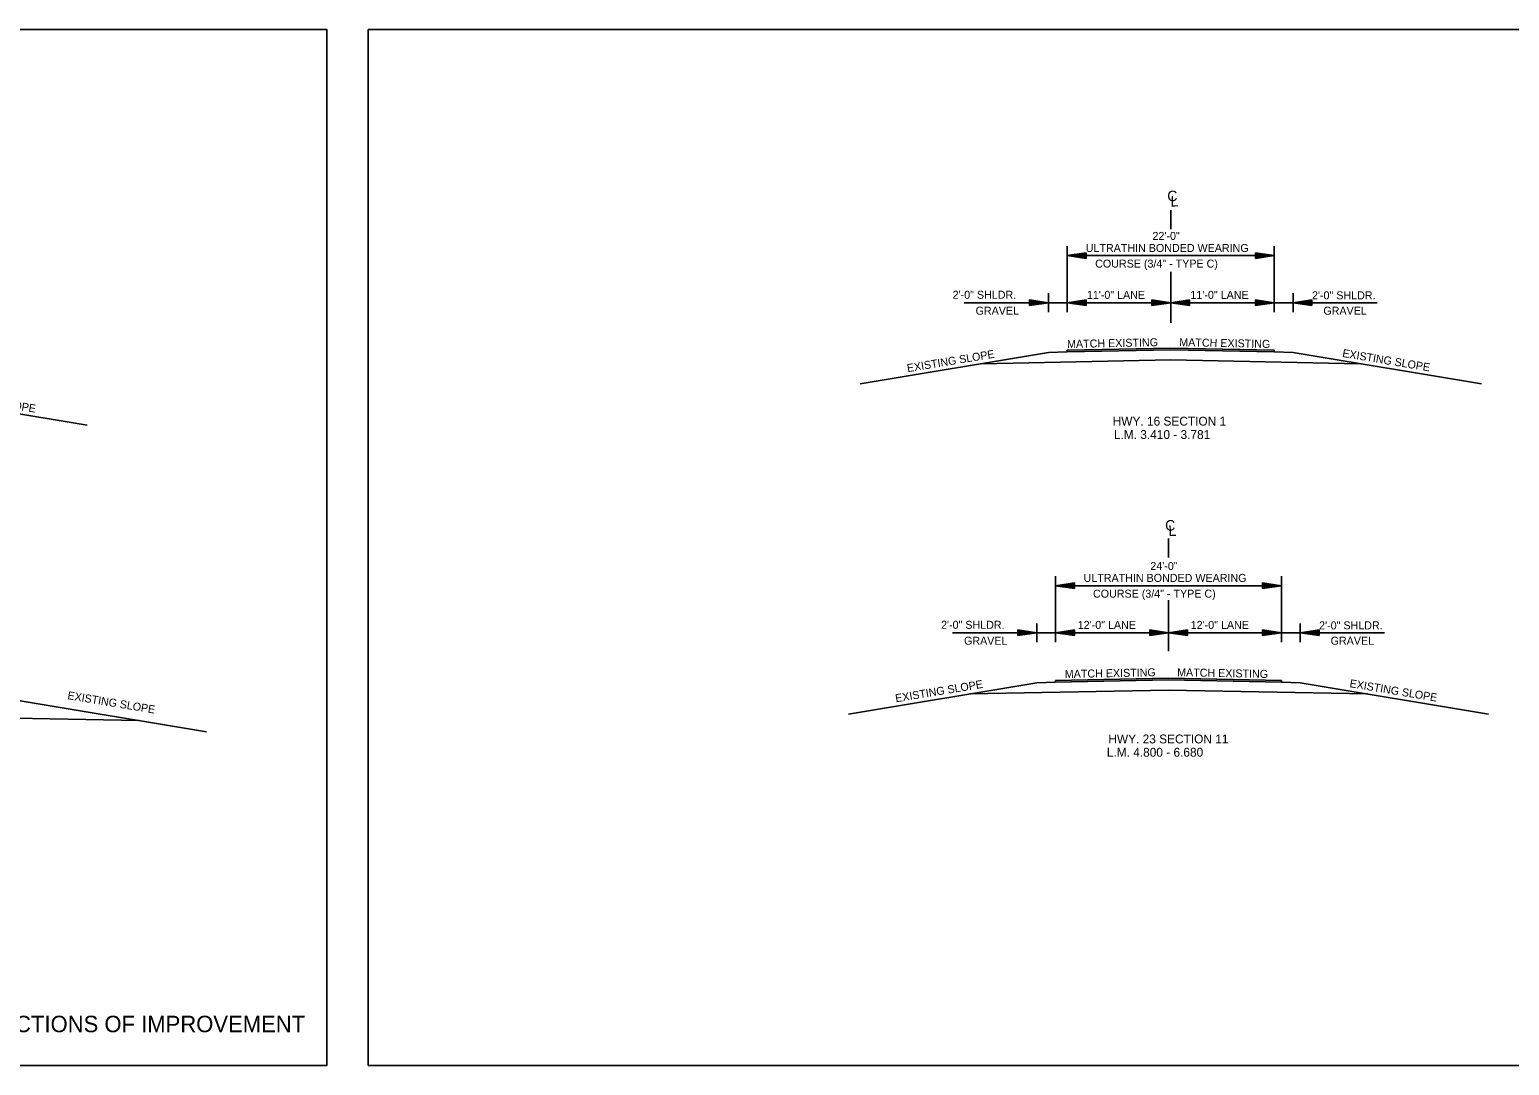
# Model space of a CAD drawing. Extents: x 2261938 to 2263136, y -3124572 to -3124216.
# Drawn here: x 2262466.5 to 2262623.7, y -3124556.1 to -3124446.1 of the extents above; entities that cross this region are included whole.
import ezdxf

# ---------------------------------------------------------------- set-up
doc = ezdxf.new("R2010")
doc.units = 0
for name, color, linetype in [('DSN_DRFT_Common-Annotations', 7, 'Continuous'), ('DSN_DRFT_Common-Line', 7, 'Continuous'), ('DSN_DRFT_Dimension', 7, 'Continuous'), ('SHET_Border-Text', 7, 'Continuous')]:
    doc.layers.add(name, color=color, linetype=linetype)

msp = doc.modelspace()

# ---------------------------------------------------------------- linework, layer by layer
at = {"layer": 'DSN_DRFT_Common-Line'}
for p, q in [((2262587.74, -3124465.28), (2262587.74, -3124467.3)), ((2262576.74, -3124469.11), (2262576.74, -3124476.11)), ((2262598.74, -3124469.11), (2262598.74, -3124476.11)), ((2262587.74, -3124471.82), (2262587.74, -3124477.23)), ((2262574.74, -3124474.11), (2262574.74, -3124476.11)), ((2262600.74, -3124474.11), (2262600.74, -3124476.11)), ((2262574.74, -3124480.41), (2262554.74, -3124483.74)), ((2262587.74, -3124481.19), (2262567.63, -3124481.6)), ((2262576.74, -3124480.33), (2262574.74, -3124480.41)), ((2262587.74, -3124479.94), (2262576.74, -3124480.16)), ((2262587.74, -3124480.11), (2262576.74, -3124480.33)), ((2262576.74, -3124480.16), (2262576.74, -3124480.33)), ((2262587.74, -3124479.94), (2262598.74, -3124480.16)), ((2262587.74, -3124480.11), (2262598.74, -3124480.33)), ((2262587.74, -3124481.19), (2262607.85, -3124481.6)), ((2262598.74, -3124480.16), (2262598.74, -3124480.33)), ((2262598.74, -3124480.33), (2262600.74, -3124480.41)), ((2262600.74, -3124480.41), (2262620.74, -3124483.74)), ((2262452.66, -3124484.8), (2262472.66, -3124488.13)), ((2262587.5, -3124500.15), (2262587.5, -3124502.18)), ((2262575.5, -3124504.16), (2262575.5, -3124511.16)), ((2262599.5, -3124504.16), (2262599.5, -3124511.16)), ((2262587.5, -3124506.7), (2262587.5, -3124512.11)), ((2262573.5, -3124509.16), (2262573.5, -3124511.16)), ((2262601.5, -3124509.16), (2262601.5, -3124511.16)), ((2262573.5, -3124515.48), (2262553.5, -3124518.81)), ((2262575.5, -3124515.4), (2262573.5, -3124515.48)), ((2262587.5, -3124515.16), (2262575.5, -3124515.4)), ((2262587.5, -3124515.16), (2262599.5, -3124515.4)), ((2262599.5, -3124515.4), (2262601.5, -3124515.48)), ((2262601.5, -3124515.48), (2262621.5, -3124518.81)), ((2262465.33, -3124517.35), (2262485.33, -3124520.68)), ((2262587.5, -3124516.24), (2262566.39, -3124516.66)), ((2262587.5, -3124516.24), (2262608.62, -3124516.66)), ((2262391.33, -3124517.75), (2262478.16, -3124519.49))]:
    msp.add_line(p, q, dxfattribs=at)
for points in [[(2262328.11, -3124446.1), (2262328.11, -3124556.1), (2262498.11, -3124556.1), (2262498.11, -3124446.1)], [(2262502.5, -3124446.1), (2262502.5, -3124556.1), (2262672.5, -3124556.1), (2262672.5, -3124446.1)], [(2262598.74, -3124480.33), (2262587.74, -3124480.11), (2262576.74, -3124480.33), (2262576.74, -3124480.16), (2262587.74, -3124479.94), (2262598.74, -3124480.16)], [(2262599.5, -3124515.4), (2262587.5, -3124515.16), (2262575.5, -3124515.4), (2262575.5, -3124515.23), (2262587.5, -3124514.99), (2262599.5, -3124515.23)]]:
    msp.add_lwpolyline(points, close=True, dxfattribs=at)
at = {"layer": 'DSN_DRFT_Dimension'}
for p, q in [((2262578.74, -3124469.81), (2262576.74, -3124470.11)), ((2262578.74, -3124470.41), (2262576.74, -3124470.11)), ((2262576.74, -3124470.11), (2262598.74, -3124470.11)), ((2262578.74, -3124469.86), (2262577.07, -3124470.11)), ((2262578.74, -3124470.36), (2262577.07, -3124470.11)), ((2262578.74, -3124469.91), (2262577.42, -3124470.11)), ((2262578.74, -3124470.31), (2262577.42, -3124470.11)), ((2262578.74, -3124469.96), (2262577.75, -3124470.11)), ((2262578.74, -3124470.26), (2262577.75, -3124470.11)), ((2262578.74, -3124470.01), (2262578.09, -3124470.11)), ((2262578.74, -3124470.21), (2262578.09, -3124470.11)), ((2262578.74, -3124470.06), (2262578.42, -3124470.11)), ((2262578.74, -3124470.16), (2262578.42, -3124470.11)), ((2262578.74, -3124469.81), (2262578.74, -3124470.41)), ((2262596.74, -3124469.81), (2262598.74, -3124470.11)), ((2262596.74, -3124469.81), (2262596.74, -3124470.41)), ((2262596.74, -3124469.86), (2262598.41, -3124470.11)), ((2262596.74, -3124469.91), (2262598.06, -3124470.11)), ((2262596.74, -3124469.96), (2262597.73, -3124470.11)), ((2262596.74, -3124470.01), (2262597.39, -3124470.11)), ((2262596.74, -3124470.06), (2262597.06, -3124470.11)), ((2262596.74, -3124470.41), (2262598.74, -3124470.11)), ((2262596.74, -3124470.21), (2262597.39, -3124470.11)), ((2262596.74, -3124470.31), (2262598.06, -3124470.11)), ((2262596.74, -3124470.36), (2262598.41, -3124470.11)), ((2262596.74, -3124470.26), (2262597.73, -3124470.11)), ((2262596.74, -3124470.16), (2262597.06, -3124470.11)), ((2262572.74, -3124474.81), (2262574.74, -3124475.11)), ((2262572.74, -3124474.81), (2262572.74, -3124475.41)), ((2262572.74, -3124474.86), (2262574.41, -3124475.11)), ((2262572.74, -3124474.91), (2262574.06, -3124475.11)), ((2262572.74, -3124474.96), (2262573.73, -3124475.11)), ((2262572.74, -3124475.01), (2262573.39, -3124475.11)), ((2262578.74, -3124474.81), (2262576.74, -3124475.11)), ((2262578.74, -3124474.86), (2262577.07, -3124475.11)), ((2262578.74, -3124474.91), (2262577.42, -3124475.11)), ((2262578.74, -3124474.96), (2262577.75, -3124475.11)), ((2262578.74, -3124475.01), (2262578.09, -3124475.11)), ((2262578.74, -3124474.81), (2262578.74, -3124475.41)), ((2262585.74, -3124474.81), (2262587.74, -3124475.11)), ((2262585.74, -3124474.81), (2262585.74, -3124475.41)), ((2262585.74, -3124474.86), (2262587.41, -3124475.11)), ((2262585.74, -3124474.91), (2262587.06, -3124475.11)), ((2262585.74, -3124474.96), (2262586.73, -3124475.11)), ((2262585.74, -3124475.01), (2262586.39, -3124475.11)), ((2262589.74, -3124474.81), (2262587.74, -3124475.11)), ((2262589.74, -3124474.86), (2262588.07, -3124475.11)), ((2262589.74, -3124474.91), (2262588.42, -3124475.11)), ((2262589.74, -3124474.96), (2262588.75, -3124475.11)), ((2262589.74, -3124475.01), (2262589.09, -3124475.11)), ((2262589.74, -3124474.81), (2262589.74, -3124475.41)), ((2262596.74, -3124474.81), (2262598.74, -3124475.11)), ((2262596.74, -3124474.81), (2262596.74, -3124475.41)), ((2262596.74, -3124474.86), (2262598.41, -3124475.11)), ((2262596.74, -3124474.91), (2262598.06, -3124475.11)), ((2262596.74, -3124474.96), (2262597.73, -3124475.11)), ((2262596.74, -3124475.01), (2262597.39, -3124475.11)), ((2262602.74, -3124474.81), (2262600.74, -3124475.11)), ((2262602.74, -3124474.86), (2262601.07, -3124475.11)), ((2262602.74, -3124474.91), (2262601.42, -3124475.11)), ((2262602.74, -3124474.96), (2262601.75, -3124475.11)), ((2262602.74, -3124475.01), (2262602.09, -3124475.11)), ((2262602.74, -3124474.81), (2262602.74, -3124475.41)), ((2262565.8, -3124475.11), (2262574.74, -3124475.11)), ((2262572.74, -3124475.06), (2262573.06, -3124475.11)), ((2262572.74, -3124475.41), (2262574.74, -3124475.11)), ((2262572.74, -3124475.21), (2262573.39, -3124475.11)), ((2262572.74, -3124475.31), (2262574.06, -3124475.11)), ((2262572.74, -3124475.36), (2262574.41, -3124475.11)), ((2262572.74, -3124475.26), (2262573.73, -3124475.11)), ((2262572.74, -3124475.16), (2262573.06, -3124475.11)), ((2262576.74, -3124475.11), (2262574.74, -3124475.11)), ((2262576.74, -3124475.11), (2262587.74, -3124475.11)), ((2262578.74, -3124475.41), (2262576.74, -3124475.11)), ((2262578.74, -3124475.36), (2262577.07, -3124475.11)), ((2262578.74, -3124475.31), (2262577.42, -3124475.11)), ((2262578.74, -3124475.26), (2262577.75, -3124475.11)), ((2262578.74, -3124475.21), (2262578.09, -3124475.11)), ((2262578.74, -3124475.06), (2262578.42, -3124475.11)), ((2262578.74, -3124475.16), (2262578.42, -3124475.11)), ((2262585.74, -3124475.06), (2262586.06, -3124475.11)), ((2262585.74, -3124475.41), (2262587.74, -3124475.11)), ((2262585.74, -3124475.21), (2262586.39, -3124475.11)), ((2262585.74, -3124475.31), (2262587.06, -3124475.11)), ((2262585.74, -3124475.36), (2262587.41, -3124475.11)), ((2262585.74, -3124475.26), (2262586.73, -3124475.11)), ((2262585.74, -3124475.16), (2262586.06, -3124475.11)), ((2262587.74, -3124475.11), (2262598.74, -3124475.11)), ((2262589.74, -3124475.41), (2262587.74, -3124475.11)), ((2262589.74, -3124475.36), (2262588.07, -3124475.11)), ((2262589.74, -3124475.31), (2262588.42, -3124475.11)), ((2262589.74, -3124475.26), (2262588.75, -3124475.11)), ((2262589.74, -3124475.21), (2262589.09, -3124475.11)), ((2262589.74, -3124475.06), (2262589.42, -3124475.11)), ((2262589.74, -3124475.16), (2262589.42, -3124475.11)), ((2262596.74, -3124475.06), (2262597.06, -3124475.11)), ((2262596.74, -3124475.41), (2262598.74, -3124475.11)), ((2262596.74, -3124475.21), (2262597.39, -3124475.11)), ((2262596.74, -3124475.31), (2262598.06, -3124475.11)), ((2262596.74, -3124475.36), (2262598.41, -3124475.11)), ((2262596.74, -3124475.26), (2262597.73, -3124475.11)), ((2262596.74, -3124475.16), (2262597.06, -3124475.11)), ((2262598.74, -3124475.11), (2262600.74, -3124475.11)), ((2262602.74, -3124475.41), (2262600.74, -3124475.11)), ((2262600.74, -3124475.11), (2262609.68, -3124475.11)), ((2262602.74, -3124475.36), (2262601.07, -3124475.11)), ((2262602.74, -3124475.31), (2262601.42, -3124475.11)), ((2262602.74, -3124475.26), (2262601.75, -3124475.11)), ((2262602.74, -3124475.21), (2262602.09, -3124475.11)), ((2262602.74, -3124475.06), (2262602.42, -3124475.11)), ((2262602.74, -3124475.16), (2262602.42, -3124475.11)), ((2262577.5, -3124504.86), (2262575.5, -3124505.16)), ((2262577.5, -3124504.91), (2262575.84, -3124505.16)), ((2262577.5, -3124504.86), (2262577.5, -3124505.46)), ((2262597.5, -3124504.86), (2262599.5, -3124505.16)), ((2262597.5, -3124504.86), (2262597.5, -3124505.46)), ((2262597.5, -3124504.91), (2262599.17, -3124505.16)), ((2262577.5, -3124505.46), (2262575.5, -3124505.16)), ((2262575.5, -3124505.16), (2262599.5, -3124505.16)), ((2262577.5, -3124505.41), (2262575.84, -3124505.16)), ((2262577.5, -3124504.96), (2262576.18, -3124505.16)), ((2262577.5, -3124505.36), (2262576.18, -3124505.16)), ((2262577.5, -3124505.01), (2262576.52, -3124505.16)), ((2262577.5, -3124505.31), (2262576.52, -3124505.16)), ((2262577.5, -3124505.06), (2262576.85, -3124505.16)), ((2262577.5, -3124505.26), (2262576.85, -3124505.16)), ((2262577.5, -3124505.11), (2262577.19, -3124505.16)), ((2262577.5, -3124505.2), (2262577.19, -3124505.16)), ((2262597.5, -3124504.96), (2262598.83, -3124505.16)), ((2262597.5, -3124505.01), (2262598.49, -3124505.16)), ((2262597.5, -3124505.06), (2262598.15, -3124505.16)), ((2262597.5, -3124505.11), (2262597.82, -3124505.16)), ((2262597.5, -3124505.46), (2262599.5, -3124505.16)), ((2262597.5, -3124505.26), (2262598.15, -3124505.16)), ((2262597.5, -3124505.36), (2262598.83, -3124505.16)), ((2262597.5, -3124505.41), (2262599.17, -3124505.16)), ((2262597.5, -3124505.31), (2262598.49, -3124505.16)), ((2262597.5, -3124505.2), (2262597.82, -3124505.16)), ((2262564.56, -3124510.16), (2262573.5, -3124510.16)), ((2262571.5, -3124509.86), (2262573.5, -3124510.16)), ((2262571.5, -3124509.86), (2262571.5, -3124510.46)), ((2262571.5, -3124509.91), (2262573.17, -3124510.16)), ((2262571.5, -3124509.96), (2262572.83, -3124510.16)), ((2262571.5, -3124510.01), (2262572.49, -3124510.16)), ((2262571.5, -3124510.06), (2262572.15, -3124510.16)), ((2262571.5, -3124510.11), (2262571.82, -3124510.16)), ((2262571.5, -3124510.46), (2262573.5, -3124510.16)), ((2262571.5, -3124510.26), (2262572.15, -3124510.16)), ((2262571.5, -3124510.36), (2262572.83, -3124510.16)), ((2262571.5, -3124510.41), (2262573.17, -3124510.16)), ((2262571.5, -3124510.31), (2262572.49, -3124510.16)), ((2262571.5, -3124510.2), (2262571.82, -3124510.16)), ((2262575.5, -3124510.16), (2262573.5, -3124510.16)), ((2262577.5, -3124509.86), (2262575.5, -3124510.16)), ((2262575.5, -3124510.16), (2262587.5, -3124510.16)), ((2262577.5, -3124510.46), (2262575.5, -3124510.16)), ((2262577.5, -3124509.91), (2262575.84, -3124510.16)), ((2262577.5, -3124510.41), (2262575.84, -3124510.16)), ((2262577.5, -3124509.96), (2262576.18, -3124510.16)), ((2262577.5, -3124510.36), (2262576.18, -3124510.16)), ((2262577.5, -3124510.01), (2262576.52, -3124510.16)), ((2262577.5, -3124510.31), (2262576.52, -3124510.16)), ((2262577.5, -3124510.06), (2262576.85, -3124510.16)), ((2262577.5, -3124510.26), (2262576.85, -3124510.16)), ((2262577.5, -3124510.11), (2262577.19, -3124510.16)), ((2262577.5, -3124510.2), (2262577.19, -3124510.16)), ((2262577.5, -3124509.86), (2262577.5, -3124510.46)), ((2262585.5, -3124509.86), (2262587.5, -3124510.16)), ((2262585.5, -3124509.86), (2262585.5, -3124510.46)), ((2262585.5, -3124509.91), (2262587.17, -3124510.16)), ((2262585.5, -3124509.96), (2262586.83, -3124510.16)), ((2262585.5, -3124510.01), (2262586.49, -3124510.16)), ((2262585.5, -3124510.06), (2262586.15, -3124510.16)), ((2262585.5, -3124510.11), (2262585.82, -3124510.16)), ((2262585.5, -3124510.46), (2262587.5, -3124510.16)), ((2262585.5, -3124510.26), (2262586.15, -3124510.16)), ((2262585.5, -3124510.36), (2262586.83, -3124510.16)), ((2262585.5, -3124510.41), (2262587.17, -3124510.16)), ((2262585.5, -3124510.31), (2262586.49, -3124510.16)), ((2262585.5, -3124510.2), (2262585.82, -3124510.16)), ((2262589.5, -3124509.86), (2262587.5, -3124510.16)), ((2262587.5, -3124510.16), (2262599.5, -3124510.16)), ((2262589.5, -3124510.46), (2262587.5, -3124510.16)), ((2262589.5, -3124509.91), (2262587.84, -3124510.16)), ((2262589.5, -3124510.41), (2262587.84, -3124510.16)), ((2262589.5, -3124509.96), (2262588.18, -3124510.16)), ((2262589.5, -3124510.36), (2262588.18, -3124510.16)), ((2262589.5, -3124510.01), (2262588.52, -3124510.16)), ((2262589.5, -3124510.31), (2262588.52, -3124510.16)), ((2262589.5, -3124510.06), (2262588.85, -3124510.16)), ((2262589.5, -3124510.26), (2262588.85, -3124510.16)), ((2262589.5, -3124510.11), (2262589.19, -3124510.16)), ((2262589.5, -3124510.2), (2262589.19, -3124510.16)), ((2262589.5, -3124509.86), (2262589.5, -3124510.46)), ((2262597.5, -3124509.86), (2262599.5, -3124510.16)), ((2262597.5, -3124509.86), (2262597.5, -3124510.46)), ((2262597.5, -3124509.91), (2262599.17, -3124510.16)), ((2262597.5, -3124509.96), (2262598.83, -3124510.16)), ((2262597.5, -3124510.01), (2262598.49, -3124510.16)), ((2262597.5, -3124510.06), (2262598.15, -3124510.16)), ((2262597.5, -3124510.11), (2262597.82, -3124510.16)), ((2262597.5, -3124510.46), (2262599.5, -3124510.16)), ((2262597.5, -3124510.26), (2262598.15, -3124510.16)), ((2262597.5, -3124510.36), (2262598.83, -3124510.16)), ((2262597.5, -3124510.41), (2262599.17, -3124510.16)), ((2262597.5, -3124510.31), (2262598.49, -3124510.16)), ((2262597.5, -3124510.2), (2262597.82, -3124510.16)), ((2262599.5, -3124510.16), (2262601.5, -3124510.16)), ((2262603.5, -3124509.86), (2262601.5, -3124510.16)), ((2262603.5, -3124510.46), (2262601.5, -3124510.16)), ((2262601.5, -3124510.16), (2262610.44, -3124510.16)), ((2262603.5, -3124509.91), (2262601.84, -3124510.16)), ((2262603.5, -3124510.41), (2262601.84, -3124510.16)), ((2262603.5, -3124509.96), (2262602.18, -3124510.16)), ((2262603.5, -3124510.36), (2262602.18, -3124510.16)), ((2262603.5, -3124510.01), (2262602.52, -3124510.16)), ((2262603.5, -3124510.31), (2262602.52, -3124510.16)), ((2262603.5, -3124510.06), (2262602.85, -3124510.16)), ((2262603.5, -3124510.26), (2262602.85, -3124510.16)), ((2262603.5, -3124510.11), (2262603.19, -3124510.16)), ((2262603.5, -3124510.2), (2262603.19, -3124510.16)), ((2262603.5, -3124509.86), (2262603.5, -3124510.46))]:
    msp.add_line(p, q, dxfattribs=at)

# ---------------------------------------------------------------- texts
at = {"layer": 'DSN_DRFT_Common-Annotations'}
for s, height, rotation, p in [('C', 1.12, 1.1458, (2262587.38, -3124464.34)), ('L', 1.12, 1.1458, (2262587.73, -3124464.9)), ('MATCH EXISTING', 0.85, 1.1458, (2262576.73, -3124479.92)), ('MATCH EXISTING', 0.85, 358.8542, (2262588.64, -3124479.72)), ('EXISTING SLOPE', 0.85, 9.462, (2262559.79, -3124482.49)), ('EXISTING SLOPE', 0.85, 350.538, (2262605.92, -3124480.86)), ('EXISTING SLOPE', 0.85, 350.538, (2262457.84, -3124485.24)), ('C', 1.12, 1.1458, (2262587.15, -3124499.32)), ('L', 1.12, 1.1458, (2262587.5, -3124499.89)), ('MATCH EXISTING', 0.85, 1.1458, (2262576.49, -3124514.97)), ('MATCH EXISTING', 0.85, 358.8542, (2262588.41, -3124514.77)), ('EXISTING SLOPE', 0.85, 9.462, (2262558.55, -3124517.55)), ('EXISTING SLOPE', 0.85, 350.538, (2262606.69, -3124515.93)), ('EXISTING SLOPE', 0.85, 350.538, (2262470.51, -3124517.2))]:
    msp.add_text(s, height=height, rotation=rotation, dxfattribs=at).set_placement(p)
for s, height, p in [('22\'-0"', 0.85, (2262585.8, -3124468.44)), ('ULTRATHIN BONDED WEARING', 0.85, (2262578.71, -3124469.72)), ('COURSE (3/4" - TYPE C)', 0.85, (2262579.71, -3124471.38)), ('2\'-0" SHLDR.', 0.85, (2262564.57, -3124474.69)), ('11\'-0" LANE', 0.85, (2262578.83, -3124474.7)), ('11\'-0" LANE', 0.85, (2262589.83, -3124474.7)), ('2\'-0" SHLDR.', 0.85, (2262602.74, -3124474.75)), ('GRAVEL', 0.85, (2262567.01, -3124476.38)), ('GRAVEL', 0.85, (2262603.95, -3124476.38)), ('HWY. 16 SECTION 1', 0.943, (2262581.57, -3124488.16)), ('L.M. 3.410 - 3.781', 0.943, (2262581.7, -3124489.58)), ('24\'-0"', 0.85, (2262585.57, -3124503.49)), ('ULTRATHIN BONDED WEARING', 0.85, (2262578.48, -3124504.76)), ('COURSE (3/4" - TYPE C)', 0.85, (2262579.48, -3124506.43)), ('2\'-0" SHLDR.', 0.85, (2262563.34, -3124509.74)), ('12\'-0" LANE', 0.85, (2262577.86, -3124509.75)), ('12\'-0" LANE', 0.85, (2262589.86, -3124509.75)), ('2\'-0" SHLDR.', 0.85, (2262603.5, -3124509.8)), ('GRAVEL', 0.85, (2262565.78, -3124511.43)), ('GRAVEL', 0.85, (2262604.72, -3124511.43)), ('HWY. 23 SECTION 11', 0.943, (2262581.11, -3124521.91)), ('L.M. 4.800 - 6.680', 0.943, (2262580.95, -3124523.32))]:
    msp.add_text(s, height=height, dxfattribs=at).set_placement(p)
at = {"layer": 'SHET_Border-Text'}
msp.add_text('TYPICAL SECTIONS OF IMPROVEMENT', height=1.75, dxfattribs=at).set_placement((2262451.46, -3124552.58))

doc.saveas('drawing.dxf')
